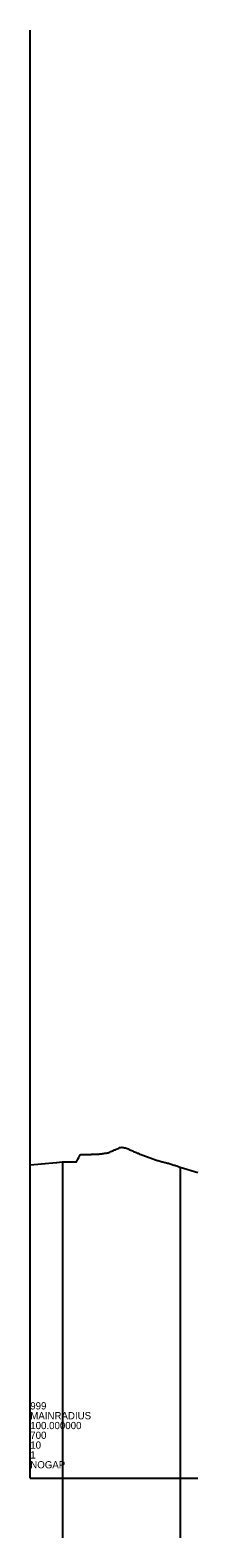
# Model space of a CAD drawing. Extents: x 1200000 to 1692190, y 507547 to 1200000.
# Drawn here: x 1689501 to 1689617, y 507547 to 508589 of the extents above; entities that cross this region are included whole.
import ezdxf

# ---------------------------------------------------------------- set-up
doc = ezdxf.new("R2010")
doc.units = 0
for name, color, linetype in [('DESIGN - SHEET - Light Grid', 7, 'Continuous'), ('DESIGN - TRANSPORTATION - Curb Gutter and Sidewalk', 7, 'Continuous'), ('SURVEY - PROFILE - Ground Line with Text', 7, 'Continuous')]:
    doc.layers.add(name, color=color, linetype=linetype)

msp = doc.modelspace()

# ---------------------------------------------------------------- linework, layer by layer
at = {"layer": 'DESIGN - SHEET - Light Grid'}
for q in [(1689501.5, 508588.6), (1689617.1, 507588.6), (1689501.5, 507588.6)]:
    msp.add_line((1689501.5, 507588.6), q, dxfattribs=at)
at = {"layer": 'DESIGN - TRANSPORTATION - Curb Gutter and Sidewalk'}
for p, q in [((1689523.7, 507806.9), (1689523.7, 507547.3)), ((1689605, 507803.4), (1689605, 507547.3))]:
    msp.add_line(p, q, dxfattribs=at)
at = {"layer": 'SURVEY - PROFILE - Ground Line with Text'}
msp.add_lwpolyline([(1689501.5, 507805), (1689519.6, 507806.6), (1689519.9, 507806.6), (1689523.6, 507806.9), (1689523.7, 507806.9), (1689524.3, 507806.9), (1689524.9, 507806.9), (1689525.5, 507807), (1689526.2, 507807), (1689526.8, 507807), (1689527.4, 507807), (1689528.1, 507807), (1689528.7, 507807), (1689529.3, 507807), (1689530, 507807), (1689530.6, 507807), (1689531.2, 507807), (1689531.9, 507807), (1689532.5, 507806.9), (1689533.3, 507806.9), (1689533.9, 507808), (1689534.4, 507808.8), (1689535, 507810), (1689536, 507811.9), (1689536.3, 507812), (1689536.9, 507812), (1689537.5, 507812), (1689538.2, 507812), (1689538.8, 507812), (1689539.4, 507812.1), (1689540, 507812.1), (1689540.7, 507812.1), (1689541.3, 507812.1), (1689541.9, 507812.1), (1689542.6, 507812.1), (1689543.2, 507812.1), (1689543.8, 507812.2), (1689544.5, 507812.2), (1689545.1, 507812.2), (1689545.7, 507812.2), (1689546.4, 507812.2), (1689547, 507812.2), (1689547.6, 507812.2), (1689547.9, 507812.2), (1689548.2, 507812.3), (1689548.9, 507812.4), (1689549.5, 507812.5), (1689550.1, 507812.6), (1689550.8, 507812.6), (1689551.4, 507812.7), (1689552, 507812.8), (1689552.7, 507812.9), (1689553.3, 507813), (1689553.9, 507813.1), (1689554.5, 507813.2), (1689555.3, 507813.3), (1689555.8, 507813.5), (1689556.4, 507813.8), (1689557.1, 507814.1), (1689557.7, 507814.3), (1689558.3, 507814.6), (1689559, 507814.9), (1689559.6, 507815.2), (1689560.2, 507815.4), (1689560.8, 507815.7), (1689561.5, 507816), (1689562.1, 507816.2), (1689562.7, 507816.5), (1689563.4, 507816.8), (1689564, 507817), (1689564.6, 507817.1), (1689565.3, 507817), (1689565.9, 507816.9), (1689566.5, 507816.7), (1689567.2, 507816.6), (1689568, 507816.4), (1689568.4, 507816.2), (1689569, 507815.9), (1689569.7, 507815.6), (1689570.3, 507815.3), (1689570.9, 507815.1), (1689571.6, 507814.8), (1689572.2, 507814.5), (1689572.8, 507814.2), (1689573.5, 507813.9), (1689574.1, 507813.7), (1689574.7, 507813.4), (1689575.3, 507813.1), (1689576, 507812.9), (1689576.6, 507812.6), (1689577.2, 507812.3), (1689577.9, 507812.1), (1689578.5, 507811.8), (1689579.1, 507811.6), (1689579.8, 507811.3), (1689580.4, 507811.1), (1689581, 507810.9), (1689581.6, 507810.6), (1689582.3, 507810.4), (1689582.9, 507810.2), (1689583.5, 507809.9), (1689584.2, 507809.7), (1689584.8, 507809.5), (1689585.4, 507809.3), (1689586.1, 507809.1), (1689586.7, 507808.8), (1689587.3, 507808.6), (1689588, 507808.4), (1689588.6, 507808.2), (1689589.2, 507808), (1689589.8, 507807.9), (1689590.5, 507807.7), (1689591.1, 507807.5), (1689591.7, 507807.3), (1689592.4, 507807.1), (1689593, 507807), (1689593.6, 507806.8), (1689594.3, 507806.6), (1689594.9, 507806.5), (1689595.5, 507806.3), (1689596.1, 507806.1), (1689596.8, 507806), (1689597.4, 507805.9), (1689598, 507805.6), (1689598.7, 507805.4), (1689599.3, 507805.1), (1689599.9, 507804.9), (1689600.6, 507804.8), (1689601.2, 507804.6), (1689601.8, 507804.4), (1689602.5, 507804.2), (1689603.1, 507804), (1689603.7, 507803.8), (1689604.3, 507803.6), (1689605, 507803.4), (1689617.1, 507799.6)], dxfattribs=at)

# ---------------------------------------------------------------- texts
at = {"layer": 'DESIGN - SHEET - Light Grid'}
for s, p in [('999', (1689501.5, 507636)), ('MAINRADIUS', (1689501.5, 507629.2)), ('100.000000', (1689501.5, 507622.4)), ('700', (1689501.5, 507615.7)), ('10', (1689501.5, 507608.9)), ('1', (1689501.5, 507602.1)), ('NOGAP', (1689501.5, 507595.3))]:
    msp.add_text(s, height=5, dxfattribs=at).set_placement(p)

doc.saveas('drawing.dxf')
